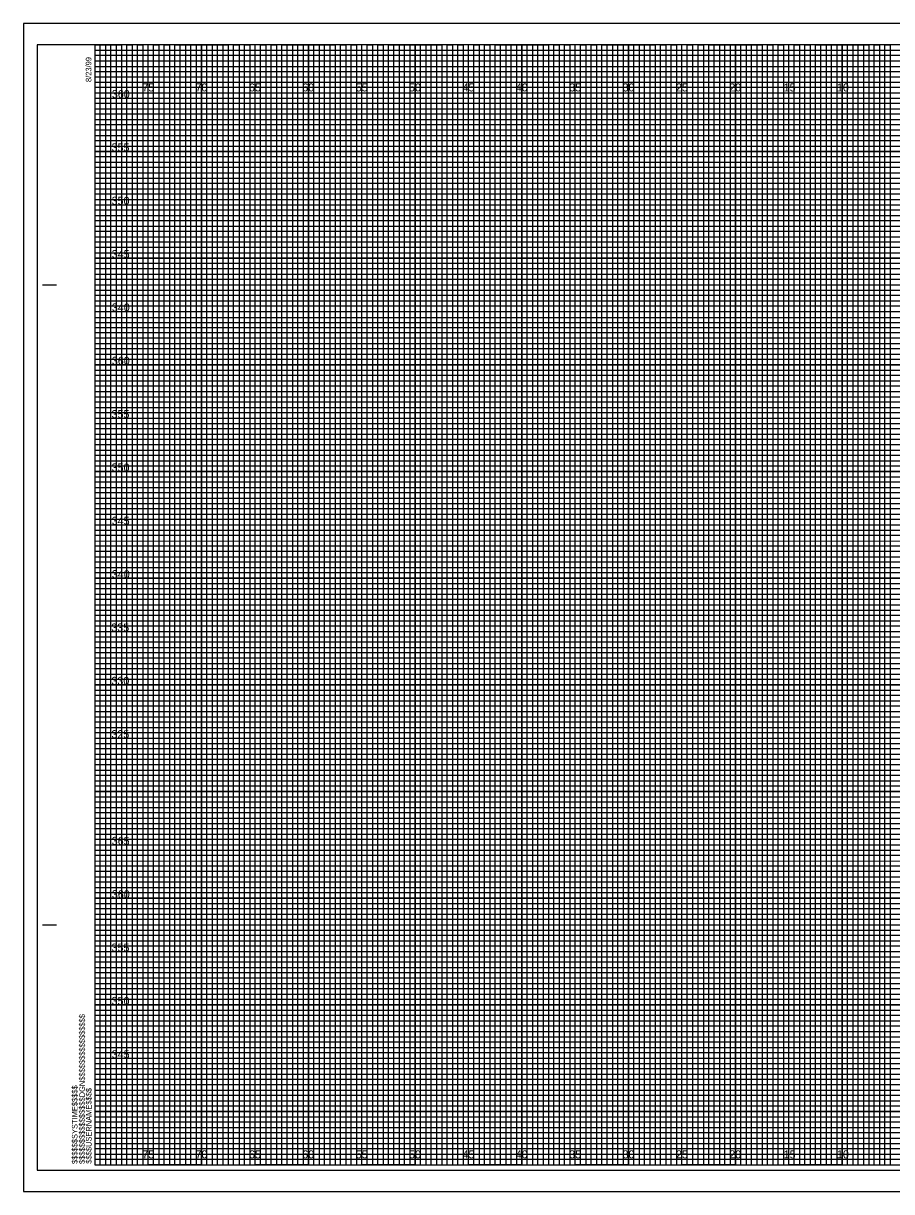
# Model space of a CAD drawing. Extents: x -7 to 266, y -5 to 437.
# Drawn here: x -6.7 to 74.6, y 107.5 to 217 of the extents above; entities that cross this region are included whole.
import ezdxf

# ---------------------------------------------------------------- set-up
doc = ezdxf.new("R2010")
doc.units = 0
for name, color, linetype in [('Exist XS Center Line Elevation Label', 7, 'Continuous'), ('Exist XS Ground Line', 7, 'Continuous'), ('Prop XS Finish Grade', 7, 'Continuous'), ('Prop XS Finish Grade Concrete', 7, 'Continuous'), ('Prop XS Finish Grade Earthwork', 7, 'Continuous'), ('Prop XS Hydro Elevations', 7, 'Continuous'), ('Prop XS Pvmt Edge Slope', 7, 'Continuous'), ('Prop XS SE Text', 7, 'Continuous'), ('Prop XS SS Elevation Text', 7, 'Continuous'), ('Prop XS Subgrade Earthwork', 7, 'Continuous'), ('Typical Guardrail CELL', 7, 'Continuous')]:
    doc.layers.add(name, color=color, linetype=linetype)

msp = doc.modelspace()

# ---------------------------------------------------------------- linework, layer by layer
at = {"layer": 'Exist XS Center Line Elevation Label'}
for points in [[(0, 215), (2.5, 215), (2.5, 110), (7.5, 110), (7.5, 215), (12.5, 215), (12.5, 110), (17.5, 110), (17.5, 215), (22.5, 215), (22.5, 110), (27.5, 110), (27.5, 215), (32.5, 215), (32.5, 110), (37.5, 110), (37.5, 215), (42.5, 215), (42.5, 110), (47.5, 110), (47.5, 215), (52.5, 215), (52.5, 110), (57.5, 110), (57.5, 215), (62.5, 215), (62.5, 110), (67.5, 110), (67.5, 215), (72.5, 215), (72.5, 110), (77.5, 110)], [(0, 212.5), (137.5, 212.5)], [(0, 202.5), (160, 202.5), (160, 207.5), (0, 207.5)], [(0, 192.5), (160, 192.5), (160, 197.5), (0, 197.5)], [(0, 182.5), (160, 182.5), (160, 187.5), (0, 187.5)], [(0, 172.5), (160, 172.5), (160, 177.5), (0, 177.5)], [(0, 162.5), (160, 162.5), (160, 167.5), (0, 167.5)], [(0, 152.5), (160, 152.5), (160, 157.5), (0, 157.5)], [(0, 142.5), (160, 142.5), (160, 147.5), (0, 147.5)], [(0, 132.5), (160, 132.5), (160, 137.5), (0, 137.5)], [(0, 122.5), (160, 122.5), (160, 127.5), (0, 127.5)], [(0, 112.5), (160, 112.5), (160, 117.5), (0, 117.5)]]:
    msp.add_lwpolyline(points, dxfattribs=at)
at = {"layer": 'Exist XS Ground Line'}
for p, q in [((5, 215), (0, 215)), ((5, 110), (5, 215)), ((15, 215), (10, 215)), ((10, 215), (10, 110)), ((15, 110), (15, 215)), ((25, 215), (20, 215)), ((20, 215), (20, 110)), ((25, 110), (25, 215)), ((35, 215), (30, 215)), ((30, 215), (30, 110)), ((35, 110), (35, 215)), ((45, 215), (40, 215)), ((40, 215), (40, 110)), ((45, 110), (45, 215)), ((55, 215), (50, 215)), ((50, 215), (50, 110)), ((55, 110), (55, 215)), ((65, 215), (60, 215)), ((60, 215), (60, 110)), ((65, 110), (65, 215)), ((75, 215), (70, 215)), ((70, 215), (70, 110)), ((10, 110), (5, 110)), ((20, 110), (15, 110)), ((30, 110), (25, 110)), ((40, 110), (35, 110)), ((50, 110), (45, 110)), ((60, 110), (55, 110)), ((70, 110), (65, 110))]:
    msp.add_line(p, q, dxfattribs=at)
for points in [[(0, 210), (160, 210), (160, 205), (0, 205)], [(0, 200), (160, 200), (160, 195), (0, 195)], [(0, 190), (160, 190), (160, 185), (0, 185)], [(0, 180), (160, 180), (160, 175), (0, 175)], [(0, 170), (160, 170), (160, 165), (0, 165)], [(0, 160), (160, 160), (160, 155), (0, 155)], [(0, 150), (160, 150), (160, 145), (0, 145)], [(0, 140), (160, 140), (160, 135), (0, 135)], [(0, 130), (160, 130), (160, 125), (0, 125)], [(0, 120), (160, 120), (160, 115), (0, 115)]]:
    msp.add_lwpolyline(points, dxfattribs=at)
at = {"layer": 'Prop XS Finish Grade'}
for p, q in [((5, 110), (5, 215)), ((10, 110), (10, 215)), ((15, 110), (15, 215)), ((20, 110), (20, 215)), ((25, 110), (25, 215)), ((30, 110), (30, 215)), ((35, 110), (35, 215)), ((40, 110), (40, 215)), ((45, 110), (45, 215)), ((50, 110), (50, 215)), ((55, 110), (55, 215)), ((60, 110), (60, 215)), ((65, 110), (65, 215)), ((70, 110), (70, 215)), ((0, 210), (160, 210)), ((0, 205), (160, 205)), ((0, 200), (160, 200)), ((0, 195), (160, 195)), ((0, 190), (160, 190)), ((0, 185), (160, 185)), ((0, 180), (160, 180)), ((0, 175), (160, 175)), ((0, 170), (160, 170)), ((0, 165), (160, 165)), ((0, 160), (160, 160)), ((0, 155), (160, 155)), ((0, 150), (160, 150)), ((0, 145), (160, 145)), ((0, 140), (160, 140)), ((0, 135), (160, 135)), ((0, 130), (160, 130)), ((0, 125), (160, 125)), ((0, 120), (160, 120)), ((0, 115), (160, 115))]:
    msp.add_line(p, q, dxfattribs=at)
at = {"layer": 'Prop XS Finish Grade Earthwork'}
msp.add_lwpolyline([(-6.7, 107.5), (161.65, 107.5), (161.65, 217), (-6.7, 217)], close=True, dxfattribs=at)
at = {"layer": 'Prop XS Hydro Elevations'}
for p, q in [((-4.9, 192.5), (-3.65, 192.5)), ((-4.85, 192.5), (-3.6, 192.5)), ((-4.9, 132.5), (-3.65, 132.5)), ((-4.85, 132.5), (-3.6, 132.5)), ((0, 110), (0, 110)), ((0, 110), (0, 110)), ((0, 110), (0, 110)), ((0, 110), (0, 110)), ((0, 110), (0, 110)), ((0, 110), (0, 110)), ((0, 110), (0, 110))]:
    msp.add_line(p, q, dxfattribs=at)
msp.add_lwpolyline([(160, 215), (0, 215), (0, 110), (160, 110)], close=True, dxfattribs=at)
at = {"layer": 'Prop XS Pvmt Edge Slope'}
msp.add_lwpolyline([(-5.4, 109.5), (161.2, 109.5), (161.2, 215), (-5.4, 215)], close=True, dxfattribs=at)
at = {"layer": 'Prop XS SE Text'}
for p, q in [((0, 214.5), (130, 214.5)), ((130, 213.99), (0, 213.99)), ((0, 213.99), (0, 213.5)), ((0, 213.5), (130, 213.5)), ((130, 212.94), (0, 212.94)), ((0, 212.94), (0, 212)), ((0, 212), (160, 212))]:
    msp.add_line(p, q, dxfattribs=at)
for points in [[(0, 211.5), (135, 211.5), (160, 211.5), (160, 211), (0, 211)], [(0, 210.5), (160, 210.5), (160, 209.5), (0, 209.5)], [(0, 209), (160, 209), (160, 208.5), (0, 208.49)], [(0, 208), (160, 208), (160, 207), (0, 207)], [(0, 206.5), (160, 206.5), (160, 206), (0, 206)], [(0, 205.5), (160, 205.5), (160, 204.5), (0, 204.5)], [(0, 204), (160, 204), (160, 203.5), (0, 203.5)], [(0, 203), (160, 203), (160, 202), (0, 202)], [(0, 201.5), (160, 201.5), (160, 201), (0, 201)], [(0, 200.5), (160, 200.5), (160, 199.5), (0, 199.5)], [(0, 199), (160, 199), (160, 198.5), (0, 198.5)], [(0, 198), (160, 198), (160, 196.97), (160, 196.5), (160, 196), (0, 196)], [(0, 197), (160, 197), (160, 196.5), (0, 196.5)], [(0, 195.5), (160, 195.5), (160, 194.5), (0, 194.52)], [(0, 194.52), (160, 194.5), (160, 194), (0, 194)], [(0, 193.5), (160, 193.5), (160, 193), (0, 193)], [(0, 192), (160, 192), (160, 191.5), (0, 191.5)], [(0, 191), (160, 191), (160, 190.5), (0, 190.5)], [(-0.04, 189.44), (160, 189.44), (160, 188.94), (-0.04, 188.94)], [(0, 188.5), (160, 188.5), (160, 188), (0, 188)], [(0, 187), (160, 187), (160, 186.5), (0, 186.5)], [(0, 186), (160, 186), (160, 185.5), (0, 185.5)], [(0, 184.5), (160, 184.5), (160, 184), (0, 184)], [(0, 183.5), (160, 183.5), (160, 183), (0, 183)], [(0, 182), (160, 182), (160, 181.5), (0, 181.5)], [(0, 181), (160, 181), (160, 180.5), (0, 180.5)], [(0, 179.5), (160, 179.5), (160, 178.99), (0, 179)], [(0, 178.5), (160, 178.5), (160, 178), (0, 178)], [(0, 177), (160, 177), (160, 176.5), (0, 176.5)], [(0, 176), (160, 176), (160, 175.5), (0, 175.5)], [(0, 174.5), (160, 174.5), (160, 174), (0, 174)], [(0, 173.5), (160, 173.5), (160, 173), (0, 173)], [(0, 172), (160, 172), (160, 171.5), (0, 171.5)], [(0, 171), (160, 171), (160, 170.5), (0, 170.5)], [(0, 169.5), (160, 169.5), (160, 169), (0, 169)], [(0, 168.5), (160.03, 168.46), (160, 168), (0, 168)], [(0, 167), (160, 167), (160, 166.5), (0, 166.5)], [(0, 166), (160, 166), (160, 165.5), (0, 165.5)], [(0, 164.5), (160, 164.5), (160, 164), (0, 164)], [(0, 163.5), (160, 163.5), (160, 163), (0, 163)], [(0, 162), (160, 162), (160, 161.5), (0, 161.5)], [(0, 161), (160, 161), (160, 160.5), (0, 160.5)], [(0, 159.5), (160, 159.5), (160, 159), (0, 159)], [(0, 158.5), (160, 158.5), (160, 158), (0, 158)], [(0, 157), (160, 157), (160, 156.5), (0, 156.5)], [(0, 156), (160, 156), (160, 155.5), (0, 155.5)], [(0, 154.5), (160, 154.5), (160, 154), (0, 154)], [(0, 153.5), (160, 153.5), (160, 153), (0, 153)], [(0, 152), (160, 152), (160, 151.5), (0, 151.5)], [(0, 151), (160, 151), (160, 150.5), (0, 150.5)], [(0, 149.5), (160, 149.5), (160, 148.99), (0, 149)], [(0, 148.5), (160, 148.5), (160, 148), (0, 148)], [(0, 147), (160, 147), (160, 146.5), (0, 146.5)], [(0, 146), (160, 146), (160, 145.5), (0, 145.5)], [(0, 144.5), (160, 144.5), (160, 144), (0, 144)], [(0, 143.5), (160, 143.5), (160, 143), (0, 143)], [(0, 142), (160, 142), (160, 141.5), (0, 141.5)], [(0, 141), (160, 141), (160, 140.5), (0, 140.5)], [(0, 139.5), (160, 139.5), (160, 139), (0, 139)], [(0, 138.5), (160.03, 138.46), (160, 138), (0, 138)], [(0, 137), (160, 137), (160, 136.5), (0, 136.5)], [(0, 136), (160, 136), (160, 135.5), (0, 135.5)], [(0, 134.5), (160, 134.5), (160, 134), (0, 134)], [(0, 133.5), (160, 133.5), (160, 133), (0, 133)], [(0, 132), (160, 132), (160, 131.5), (0, 131.5)], [(0, 131), (160, 131), (160, 130.5), (0, 130.5)], [(0, 129.5), (160, 129.5), (160, 129), (0, 129)], [(0, 128.5), (160, 128.5), (160, 128), (0, 128)], [(0, 127), (160, 127), (160, 126.5), (0, 126.5)], [(0, 126), (160, 126), (160, 125.5), (0, 125.5)], [(0, 124.5), (160, 124.5), (160, 124), (0, 124)], [(0, 123.5), (160, 123.5), (160, 123), (0, 123)], [(0, 122), (160, 122), (160, 121.5), (0, 121.5)], [(0, 121), (160, 121), (160, 120.5), (0, 120.5)], [(0, 119.5), (160, 119.5), (160, 119), (0, 119)], [(0, 118.5), (160, 118.5), (160, 118), (0, 118)], [(0, 117), (160, 117), (160, 116.5), (0, 116.5)], [(0, 116), (160, 116), (160, 115.5), (0, 115.5)], [(0, 114.5), (160, 114.5), (160, 114), (0, 114)], [(0, 113.5), (160, 113.5), (160, 113), (0, 113)], [(0, 112), (160, 112), (160, 111.5), (0, 111.5)], [(0, 111), (160, 111), (160, 110.5), (0, 110.5)]]:
    msp.add_lwpolyline(points, dxfattribs=at)
at = {"layer": 'Prop XS SS Elevation Text'}
for points in [[(0, 110), (0.5, 110), (0.5, 215), (1, 215), (1, 110)], [(1, 110), (1.5, 110), (1.5, 215), (2, 215), (2, 110)], [(2.5, 110), (3, 110), (3, 215), (3.5, 215), (3.5, 110)], [(3.5, 110), (4, 110), (4, 215), (4.5, 215), (4.5, 110)], [(5, 110), (5.5, 110), (5.5, 215), (6, 215), (6, 110)], [(6, 110), (6.5, 110), (6.5, 215), (7, 215), (7, 110)], [(7.5, 110), (8, 110), (8, 215), (8.5, 215), (8.5, 110)], [(8.5, 110), (9, 110), (9, 215), (9.5, 215), (9.5, 110)], [(10, 110), (10.5, 110), (10.5, 215), (11, 215), (11, 110)], [(11, 110), (11.5, 110), (11.5, 215), (12, 215), (12, 110)], [(12.5, 110), (13, 110), (13, 215), (13.5, 215), (13.5, 110)], [(13.5, 110), (14, 110), (14, 215), (14.5, 215), (14.5, 110)], [(15, 110), (15.5, 110), (15.5, 215), (16, 215), (16, 110)], [(16, 110), (16.5, 110), (16.5, 215), (17, 215), (17, 110)], [(17.5, 110), (18, 110), (18, 215), (18.5, 215), (18.5, 110)], [(18.5, 110), (19, 110), (19, 215), (19.5, 215), (19.5, 110)], [(20, 110), (20.5, 110), (20.5, 215), (21, 215), (21, 110)], [(21, 110), (21.5, 110), (21.5, 215), (22, 215), (22, 110)], [(22.5, 110), (23, 110), (23, 215), (23.5, 215), (23.5, 110)], [(23.5, 110), (24, 110), (24, 215), (24.5, 215), (24.5, 110)], [(25, 110), (25.5, 110), (25.5, 215), (26, 215), (26, 110)], [(26, 110), (26.5, 110), (26.5, 215), (27, 215), (27, 110)], [(27.5, 110), (28, 110), (28, 215), (28.5, 215), (28.5, 110)], [(28.5, 110), (29, 110), (29, 215), (29.5, 215), (29.5, 110)], [(30, 110), (30.5, 110), (30.5, 215), (31, 215), (31, 110)], [(31, 110), (31.5, 110), (31.5, 215), (32, 215), (32, 110)], [(32.5, 110), (33, 110), (33, 215), (33.5, 215), (33.5, 110)], [(33.5, 110), (34, 110), (34, 215), (34.5, 215), (34.5, 110)], [(35, 110), (35.5, 110), (35.5, 215), (36, 215), (36, 110)], [(36, 110), (36.5, 110), (36.5, 215), (37, 215), (37, 110)], [(37.5, 110), (38, 110), (38, 215), (38.5, 215), (38.5, 110)], [(38.5, 110), (39, 110), (39, 215), (39.5, 215), (39.5, 110)], [(40, 110), (40.5, 110), (40.5, 215), (41, 215), (41, 110)], [(41, 110), (41.5, 110), (41.5, 215), (42, 215), (42, 110)], [(42.5, 110), (43, 110), (43, 215), (43.5, 215), (43.5, 110)], [(43.5, 110), (44, 110), (44, 215), (44.5, 215), (44.5, 110)], [(45, 110), (45.5, 110), (45.5, 215), (46, 215), (46, 110)], [(46, 110), (46.5, 110), (46.5, 215), (47, 215), (47, 110)], [(47.5, 110), (48, 110), (48, 215), (48.5, 215), (48.5, 110)], [(48.5, 110), (49, 110), (49, 215), (49.5, 215), (49.5, 110)], [(50, 110), (50.5, 110), (50.5, 215), (51, 215), (51, 110)], [(51, 110), (51.5, 110), (51.5, 215), (52, 215), (52, 110)], [(52.5, 110), (53, 110), (53, 215), (53.5, 215), (53.5, 110)], [(53.5, 110), (54, 110), (54, 215), (54.5, 215), (54.5, 110)], [(55, 110), (55.5, 110), (55.5, 215), (56, 215), (56, 110)], [(56, 110), (56.5, 110), (56.5, 215), (57, 215), (57, 110)], [(57.5, 110), (58, 110), (58, 215), (58.5, 215), (58.5, 110)], [(58.5, 110), (59, 110), (59, 215), (59.5, 215), (59.5, 110)], [(60, 110), (60.5, 110), (60.5, 215), (61, 215), (61, 110)], [(61, 110), (61.5, 110), (61.5, 215), (62, 215), (62, 110)], [(62.5, 110), (63, 110), (63, 215), (63.5, 215), (63.5, 110)], [(63.5, 110), (64, 110), (64, 215), (64.5, 215), (64.5, 110)], [(65, 110), (65.5, 110), (65.5, 215), (66, 215), (66, 110)], [(66, 110), (66.5, 110), (66.5, 215), (67, 215), (67, 110)], [(67.5, 110), (68, 110), (68, 215), (68.5, 215), (68.5, 110)], [(68.5, 110), (69, 110), (69, 215), (69.5, 215), (69.5, 110)], [(70, 110), (70.5, 110), (70.5, 215), (71, 215), (71, 110)], [(71, 110), (71.5, 110), (71.5, 215), (72, 215), (72, 110)], [(72.5, 110), (73, 110), (73, 215), (73.5, 215), (73.5, 110)], [(73.5, 110), (74, 110), (74, 215), (74.5, 215), (74.5, 110)]]:
    msp.add_lwpolyline(points, dxfattribs=at)
at = {"layer": 'Prop XS Subgrade Earthwork'}
for p, q in [((161.65, 217), (-6.7, 217)), ((-6.7, 217), (-6.7, 107.5)), ((-6.7, 107.5), (161.65, 107.5))]:
    msp.add_line(p, q, dxfattribs=at)

# ---------------------------------------------------------------- texts
at = {"layer": 'Prop XS Finish Grade Concrete'}
for s, p in [('360', (1.59, 210)), ('355', (1.56, 205)), ('350', (1.57, 200)), ('345', (1.58, 195)), ('340', (1.59, 190)), ('360', (1.59, 185)), ('355', (1.56, 180)), ('350', (1.57, 175)), ('345', (1.58, 170)), ('340', (1.59, 165)), ('335', (1.54, 160)), ('330', (1.55, 155)), ('325', (1.55, 150)), ('365', (1.58, 140)), ('360', (1.59, 135)), ('355', (1.56, 130)), ('350', (1.57, 125)), ('345', (1.58, 120))]:
    msp.add_text(s, height=0.75, dxfattribs=at).set_placement(p)
at = {"layer": 'Prop XS Hydro Elevations'}
for s, p in [('8/23/99', (-0.33, 211.5)), ('$$$$$$$$$$$$$$$$DGN$$$$$$$$$$$$$$$$', (-0.94, 110.09)), ('$$$$$$SYSTIME$$$$$', (-1.63, 110.09)), ('$$$$USERNAME$$$$', (-0.31, 110.12))]:
    msp.add_text(s, height=0.525, rotation=90, dxfattribs=at).set_placement(p)
at = {"layer": 'Typical Guardrail CELL'}
for s, p in [('75', (4.44, 210.62)), ('70', (9.43, 210.62)), ('65', (14.44, 210.62)), ('60', (19.43, 210.62)), ('55', (24.44, 210.62)), ('50', (29.43, 210.62)), ('45', (34.44, 210.62)), ('40', (39.43, 210.62)), ('35', (44.44, 210.62)), ('30', (49.43, 210.62)), ('25', (54.44, 210.62)), ('20', (59.43, 210.62)), ('15', (64.53, 210.62)), ('10', (69.52, 210.62)), ('75', (4.44, 110.62)), ('70', (9.43, 110.62)), ('65', (14.44, 110.62)), ('60', (19.43, 110.62)), ('55', (24.44, 110.62)), ('50', (29.43, 110.62)), ('45', (34.44, 110.62)), ('40', (39.43, 110.62)), ('35', (44.44, 110.62)), ('30', (49.43, 110.62)), ('25', (54.44, 110.62)), ('20', (59.43, 110.62)), ('15', (64.53, 110.62)), ('10', (69.52, 110.62))]:
    msp.add_text(s, height=0.75, dxfattribs=at).set_placement(p)

doc.saveas('drawing.dxf')
